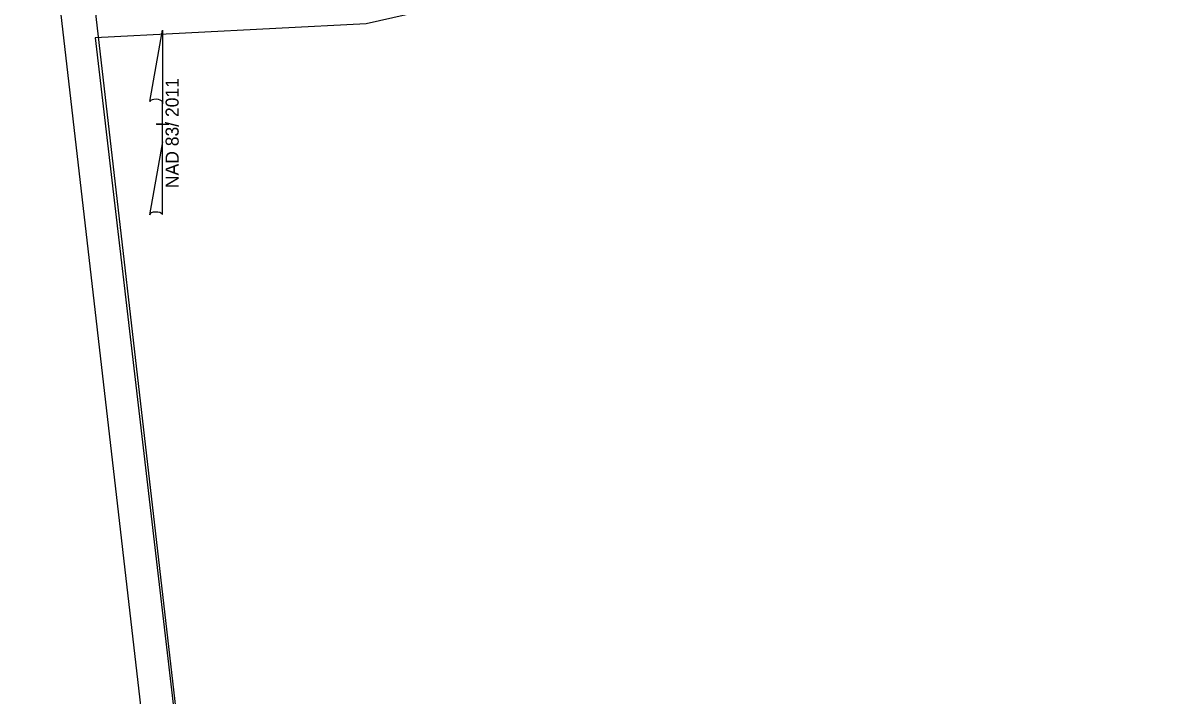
# Model space of a CAD drawing. Extents: x 477658 to 478938, y 495105 to 496902.
# Drawn here: x 477658 to 478408, y 496123 to 496559 of the extents above; entities that cross this region are included whole.
import ezdxf

# ---------------------------------------------------------------- set-up
doc = ezdxf.new("R2010")
doc.units = 0
for name, color, linetype in [('Prop North Arrow NAD83 for Plan Sheets CELL', 7, 'Continuous'), ('Sheet Clip Boundary CELL', 7, 'Continuous'), ('Sheet Plan CELL', 7, 'Continuous'), ('Sheet Plot Border Outside CELL', 7, 'Continuous')]:
    doc.layers.add(name, color=color, linetype=linetype)

msp = doc.modelspace()

# ---------------------------------------------------------------- linework, layer by layer
at = {"layer": 'Prop North Arrow NAD83 for Plan Sheets CELL'}
for p, q in [((477739.85, 496508.48), (477748.05, 496554.83)), ((477748.1, 496554.83), (477748.05, 496554.83)), ((477748.1, 496554.83), (477748.05, 496554.83)), ((477748.1, 496554.83), (477748.1, 496507.03)), ((477748.1, 496482.23), (477748.1, 496508.43)), ((477748.1, 496507.03), (477748.1, 496508.38)), ((477744.1, 496493.83), (477744.05, 496493.83)), ((477747.65, 496493.83), (477744.1, 496493.83)), ((477744.15, 496493.83), (477752.15, 496493.83)), ((477748.1, 496482.23), (477739.75, 496434.98)), ((477748.15, 496435.18), (477748.1, 496482.23))]:
    msp.add_line(p, q, dxfattribs=at)
for centre, start_param, end_param in [((477743.98, 496507.99), 0.216388, 2.908219), ((477743.98, 496434.82), 0.201328, 3.141593)]:
    msp.add_ellipse(centre, major_axis=(4.23, -0.03), ratio=0.461098, start_param=start_param, end_param=end_param, dxfattribs=at)
at = {"layer": 'Sheet Clip Boundary CELL'}
msp.add_lwpolyline([(477845.73, 495342.55), (478204.11, 495401.95), (478559.24, 495460.98), (478888.82, 495462.83), (478777.82, 496425.48), (478728.89, 496419.84), (478695.67, 496707.95), (478665.11, 496704.42), (478657.23, 496772.74), (478394.84, 496742.97), (478037.74, 496697.38), (477976.07, 496642.45), (477980.97, 496608.61), (477984.15, 496582.58), (477880.19, 496558.85), (477880.19, 496558.85), (477704.46, 496549.97)], close=True, dxfattribs=at)
at = {"layer": 'Sheet Plan CELL'}
msp.add_lwpolyline([(477681.97, 496762.78), (477853.79, 495272.62), (478896.88, 495392.89), (478725.06, 496883.03)], close=True, dxfattribs=at)
at = {"layer": 'Sheet Plot Border Outside CELL'}
msp.add_lwpolyline([(478938.31, 495230.08), (478745.48, 496902.5), (477657.69, 496777.07), (477850.52, 495104.65)], close=True, dxfattribs=at)

# ---------------------------------------------------------------- texts
at = {"layer": 'Prop North Arrow NAD83 for Plan Sheets CELL'}
msp.add_text('NAD 83/ 2011', height=8.5, rotation=90, dxfattribs=at).set_placement((477758.62, 496452.32))

doc.saveas('drawing.dxf')
